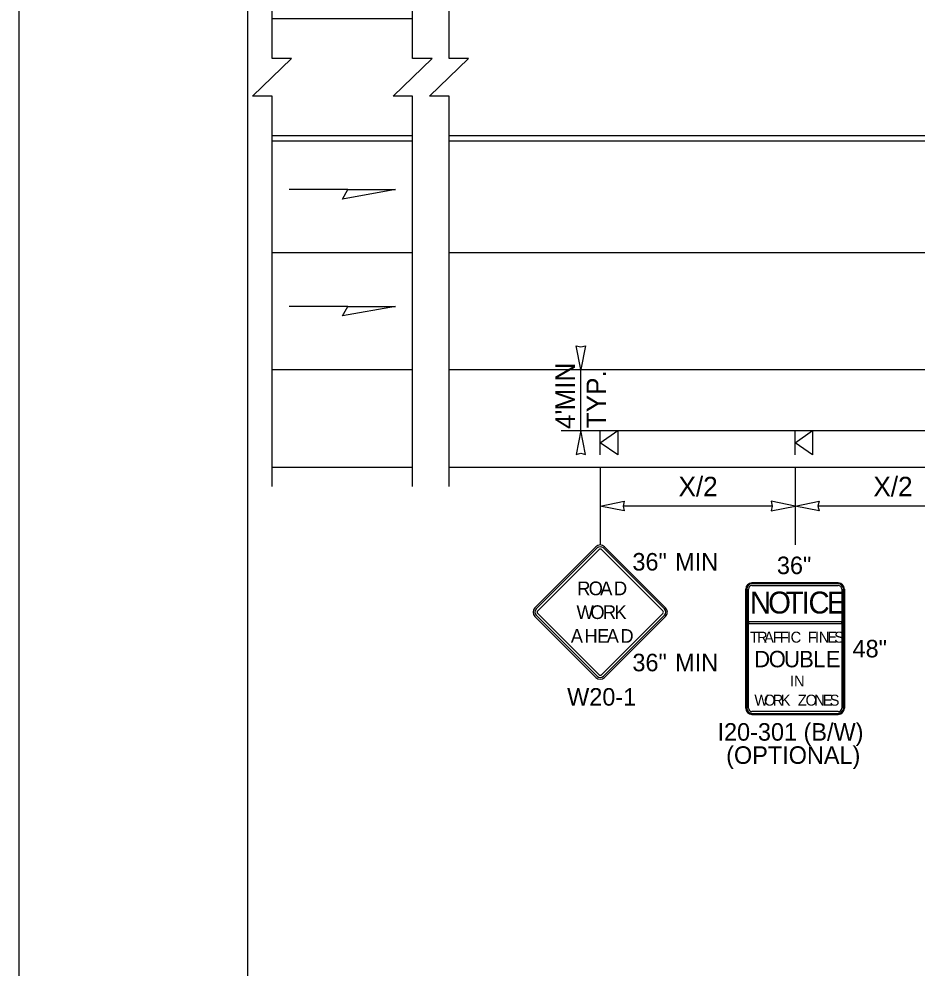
# Model space of a CAD drawing. Extents: x 99999.1 to 100096.1, y 99995 to 100010.7.
# Drawn here: x 100059.062 to 100062.749, y 100002.928 to 100006.826 of the extents above; entities that cross this region are included whole.
import ezdxf

# ---------------------------------------------------------------- set-up
doc = ezdxf.new("R2010")
doc.units = 0
for name, color, linetype in [('RD_ED_ShoulderPavedEdge', 7, 'Continuous'), ('RD_MK_LineEdgeWhite', 7, 'Continuous'), ('RD_MK_LineLane', 7, 'Continuous'), ('RD_MK_LineTwoWayLtTurn', 7, 'Continuous'), ('SH_GI_PlotLimits', 7, 'Continuous'), ('SH_GI_SheetBorder', 7, 'Continuous'), ('TR_SN_ConstructionSigns', 7, 'Continuous'), ('TR_WZ_PortableSignMountBlk-Org', 7, 'Continuous'), ('TR_WZ_PortableSignMountBlk-Wht', 7, 'Continuous'), ('TR_WZ_WorkZoneDetails', 7, 'Continuous'), ('TR_WZ_WorkZoneTextCurrent', 7, 'Continuous')]:
    doc.layers.add(name, color=color, linetype=linetype)

msp = doc.modelspace()

# ---------------------------------------------------------------- linework, layer by layer
at = {"layer": 'RD_ED_ShoulderPavedEdge'}
for p, q in [((100060.1016, 100004.9857), (100060.6783, 100004.9857)), ((100060.8283, 100004.9857), (100074.8933, 100004.9857))]:
    msp.add_line(p, q, dxfattribs=at)
at = {"layer": 'RD_MK_LineEdgeWhite'}
for p, q in [((100060.1016, 100005.3857), (100060.6783, 100005.3857)), ((100060.8283, 100005.3857), (100074.8933, 100005.3857))]:
    msp.add_line(p, q, dxfattribs=at)
at = {"layer": 'RD_MK_LineLane'}
for points in [[(100060.6783, 100005.8657), (100060.1016, 100005.8657)], [(100074.8933, 100005.8657), (100060.8283, 100005.8657)]]:
    msp.add_lwpolyline(points, dxfattribs=at)
at = {"layer": 'RD_MK_LineTwoWayLtTurn'}
for p, q in [((100060.1016, 100006.3257), (100060.6783, 100006.3257)), ((100060.8283, 100006.3257), (100074.8933, 100006.3257))]:
    msp.add_line(p, q, dxfattribs=at)
for points in [[(100060.6783, 100006.8257), (100060.1016, 100006.8257)], [(100060.6783, 100006.3457), (100060.1016, 100006.3457)], [(100074.8933, 100006.3457), (100060.8283, 100006.3457)]]:
    msp.add_lwpolyline(points, dxfattribs=at)
at = {"layer": 'SH_GI_PlotLimits'}
msp.add_lwpolyline([(100059.0625, 99999.6875), (100076.0625, 99999.6875), (100076.0625, 100010.6875), (100059.0625, 100010.6875)], close=True, dxfattribs=at)
at = {"layer": 'SH_GI_SheetBorder'}
msp.add_line((100060, 100010.375), (100060, 100000), dxfattribs=at)
at = {"layer": 'TR_SN_ConstructionSigns'}
for p, q in [((100061.4307, 100004.6583), (100061.1801, 100004.4077)), ((100061.4357, 100004.6533), (100061.1851, 100004.4028)), ((100061.1921, 100004.3958), (100061.4426, 100004.6464)), ((100061.4546, 100004.6464), (100061.7052, 100004.3958)), ((100061.7121, 100004.4028), (100061.4615, 100004.6533)), ((100061.7171, 100004.4077), (100061.4665, 100004.6583)), ((100062.0461, 100003.9953), (100062.0461, 100004.4847)), ((100062.0461, 100004.4847), (100062.0461, 100003.9953)), ((100062.0461, 100004.4847), (100062.0461, 100003.9953)), ((100062.0503, 100004.4847), (100062.0503, 100003.9953)), ((100062.0574, 100004.3504), (100062.0574, 100004.4847)), ((100062.0714, 100004.51), (100062.4258, 100004.51)), ((100062.4258, 100004.51), (100062.0714, 100004.51)), ((100062.4258, 100004.51), (100062.0714, 100004.51)), ((100062.4258, 100004.5058), (100062.0714, 100004.5058)), ((100062.0714, 100004.4988), (100062.4258, 100004.4988)), ((100062.4399, 100004.4847), (100062.4399, 100004.3504)), ((100062.4469, 100003.9953), (100062.4469, 100004.4847)), ((100062.4511, 100004.4847), (100062.4511, 100003.9953)), ((100062.4511, 100003.9953), (100062.4511, 100004.4847)), ((100062.4511, 100003.9953), (100062.4511, 100004.4847)), ((100061.1801, 100004.3719), (100061.4307, 100004.1214)), ((100061.1851, 100004.3769), (100061.4357, 100004.1263)), ((100061.4426, 100004.1333), (100061.1921, 100004.3839)), ((100061.7052, 100004.3839), (100061.4546, 100004.1333)), ((100061.4615, 100004.1263), (100061.7121, 100004.3769)), ((100061.4665, 100004.1214), (100061.7171, 100004.3719)), ((100062.0574, 100004.3504), (100062.0574, 100004.3504)), ((100062.4399, 100004.3504), (100062.0574, 100004.3504)), ((100062.0574, 100004.3504), (100062.0574, 100004.3434)), ((100062.0574, 100004.3434), (100062.0574, 100004.3504)), ((100062.0574, 100004.3434), (100062.4399, 100004.3434)), ((100062.0574, 100003.9953), (100062.0574, 100004.3434)), ((100062.4399, 100004.3434), (100062.4399, 100004.3504)), ((100062.4399, 100004.3504), (100062.4399, 100004.3434)), ((100062.4399, 100004.3434), (100062.4399, 100003.9953)), ((100062.4258, 100003.9813), (100062.0714, 100003.9813)), ((100062.0714, 100003.9742), (100062.4258, 100003.9742)), ((100062.4258, 100003.97), (100062.0714, 100003.97)), ((100062.0714, 100003.97), (100062.4258, 100003.97)), ((100062.0714, 100003.97), (100062.4258, 100003.97))]:
    msp.add_line(p, q, dxfattribs=at)
for centre, radius, start, end in [((100061.4486, 100004.6404), 0.0253, 45, 135), ((100061.4486, 100004.6404), 0.0183, 45, 135), ((100061.4486, 100004.6404), 0.00844, 45, 135), ((100062.0714, 100004.4847), 0.0253, 90, 180), ((100062.0714, 100004.4847), 0.0253, 90, 180), ((100062.0714, 100004.4847), 0.0253, 90, 180), ((100062.0714, 100004.4847), 0.0211, 90, 180), ((100062.0714, 100004.4847), 0.0141, 90, 180), ((100062.4258, 100004.4847), 0.0253, 0, 90), ((100062.4258, 100004.4847), 0.0253, 0, 90), ((100062.4258, 100004.4847), 0.0253, 0, 90), ((100062.4258, 100004.4847), 0.0211, 0, 90), ((100062.4258, 100004.4847), 0.0141, 0, 90), ((100061.198, 100004.3898), 0.0253, 135, 225), ((100061.198, 100004.3898), 0.0183, 135, 225), ((100061.6992, 100004.3898), 0.0183, 315, 45), ((100061.6992, 100004.3898), 0.0253, 315, 45), ((100061.198, 100004.3898), 0.00844, 135, 225), ((100061.6992, 100004.3898), 0.00844, 315, 45), ((100061.4486, 100004.1393), 0.00844, 225, 315), ((100061.4486, 100004.1393), 0.0253, 225, 315), ((100061.4486, 100004.1393), 0.0183, 225, 315), ((100062.0714, 100003.9953), 0.0253, 180, 270), ((100062.0714, 100003.9953), 0.0253, 180, 270), ((100062.0714, 100003.9953), 0.0253, 180, 270), ((100062.0714, 100003.9953), 0.0211, 180, 270), ((100062.0714, 100003.9953), 0.0141, 180, 270), ((100062.4258, 100003.9953), 0.0253, 270, 0), ((100062.4258, 100003.9953), 0.0253, 270, 0), ((100062.4258, 100003.9953), 0.0211, 270, 0), ((100062.4258, 100003.9953), 0.0141, 270, 0), ((100062.4258, 100003.9953), 0.0253, 270, 0)]:
    msp.add_arc(centre, radius, start, end, dxfattribs=at)
at = {"layer": 'TR_WZ_PortableSignMountBlk-Org'}
msp.add_line((100061.4486, 100005.0358), (100061.4486, 100005.1358), dxfattribs=at)
msp.add_lwpolyline([(100061.4486, 100005.0857), (100061.5204, 100005.1358), (100061.5204, 100005.0358)], close=True, dxfattribs=at)
at = {"layer": 'TR_WZ_PortableSignMountBlk-Wht'}
msp.add_line((100062.2486, 100005.0357), (100062.2486, 100005.1357), dxfattribs=at)
msp.add_lwpolyline([(100062.2486, 100005.0856), (100062.3204, 100005.1357), (100062.3204, 100005.0357)], close=True, dxfattribs=at)
at = {"layer": 'TR_WZ_WorkZoneDetails'}
for p, q in [((100060.4123, 100006.125), (100060.1712, 100006.125)), ((100060.4123, 100005.645), (100060.1712, 100005.645)), ((100061.2886, 100005.3857), (100061.4486, 100005.3857)), ((100061.3686, 100005.1358), (100061.3686, 100005.3857)), ((100061.2886, 100005.1358), (100061.4486, 100005.1358)), ((100061.4486, 100005.1358), (100065.9101, 100005.1358)), ((100061.4486, 100004.9857), (100061.4486, 100004.6657)), ((100062.2486, 100004.986), (100062.2486, 100004.6657)), ((100062.1549, 100004.8257), (100061.5423, 100004.8257)), ((100062.9549, 100004.8257), (100062.3423, 100004.8257))]:
    msp.add_line(p, q, dxfattribs=at)
for points in [[(100060.1016, 100004.9057), (100060.1016, 100006.5083), (100060.0216, 100006.5083), (100060.1817, 100006.6632), (100060.1016, 100006.6632), (100060.1016, 100008.2657)], [(100060.6783, 100004.9057), (100060.6783, 100006.5083), (100060.5983, 100006.5083), (100060.7583, 100006.6632), (100060.6783, 100006.6632), (100060.6783, 100008.2657)], [(100060.8283, 100004.9057), (100060.8283, 100006.5083), (100060.7483, 100006.5083), (100060.9083, 100006.6632), (100060.8283, 100006.6632), (100060.8283, 100008.2657)]]:
    msp.add_lwpolyline(points, dxfattribs=at)
for points in [[(100060.6088, 100006.125), (100060.39, 100006.0864), (100060.4123, 100006.125)], [(100060.6088, 100005.645), (100060.39, 100005.6064), (100060.4123, 100005.645)], [(100061.3686, 100005.3857), (100061.3493, 100005.484), (100061.3686, 100005.4795), (100061.3879, 100005.484)], [(100061.3686, 100005.1358), (100061.3493, 100005.0375), (100061.3686, 100005.0421), (100061.3879, 100005.0375)], [(100061.4486, 100004.8257), (100061.5469, 100004.845), (100061.5423, 100004.8257), (100061.5469, 100004.8065)], [(100062.2486, 100004.8257), (100062.1503, 100004.845), (100062.1549, 100004.8257), (100062.1503, 100004.8065)], [(100062.2486, 100004.8257), (100062.3469, 100004.845), (100062.3423, 100004.8257), (100062.3469, 100004.8065)]]:
    msp.add_lwpolyline(points, close=True, dxfattribs=at)

# ---------------------------------------------------------------- texts
at = {"layer": 'TR_SN_ConstructionSigns'}
for s, p in [('36"', (100061.5807, 100004.5607)), ('MIN', (100061.7562, 100004.5607)), ('36"', (100062.1738, 100004.546)), ('48"', (100062.4844, 100004.204)), ('36"', (100061.5807, 100004.147)), ('MIN', (100061.7562, 100004.147)), ('W20-1', (100061.3128, 100004.0059)), ('I20-301 (B/W)', (100061.93, 100003.862)), ('(OPTIONAL)', (100061.9655, 100003.7669))]:
    msp.add_text(s, height=0.072, rotation=360, dxfattribs=at).set_placement(p)
for s, height, p in [('R', 0.0562, (100061.354, 100004.4594)), ('O', 0.0562, (100061.401, 100004.4594)), ('A', 0.0562, (100061.4484, 100004.4594)), ('D', 0.0562, (100061.5049, 100004.4594)), ('N', 0.09, (100062.0629, 100004.3842)), ('O', 0.09, (100062.1379, 100004.3842)), ('T', 0.09, (100062.21, 100004.3842)), ('I', 0.09, (100062.2753, 100004.3842)), ('C', 0.09, (100062.3035, 100004.3842)), ('E', 0.09, (100062.3786, 100004.3842)), ('W', 0.0562, (100061.3511, 100004.3617)), ('O', 0.0562, (100061.408, 100004.3617)), ('R', 0.0562, (100061.4595, 100004.3617)), ('K', 0.0562, (100061.5067, 100004.3617)), ('A', 0.0562, (100061.3277, 100004.264)), ('H', 0.0562, (100061.3839, 100004.264)), ('E', 0.0562, (100061.4357, 100004.264)), ('A', 0.0562, (100061.4751, 100004.264)), ('D', 0.0562, (100061.5313, 100004.264)), ('T', 0.045, (100062.0628, 100004.2646)), ('R', 0.045, (100062.092, 100004.2646)), ('A', 0.045, (100062.1213, 100004.2646)), ('F', 0.045, (100062.1564, 100004.2646)), ('F', 0.045, (100062.1856, 100004.2646)), ('I', 0.045, (100062.2149, 100004.2646)), ('C', 0.045, (100062.2302, 100004.2646)), ('F', 0.045, (100062.3004, 100004.2646)), ('I', 0.045, (100062.3296, 100004.2646)), ('N', 0.045, (100062.3458, 100004.2646)), ('E', 0.045, (100062.3809, 100004.2646)), ('S', 0.045, (100062.4093, 100004.2646)), ('D', 0.0675, (100062.0809, 100004.1634)), ('O', 0.0675, (100062.1403, 100004.1634)), ('U', 0.0675, (100062.2031, 100004.1634)), ('B', 0.0675, (100062.2652, 100004.1634)), ('L', 0.0675, (100062.3225, 100004.1634)), ('E', 0.0675, (100062.3745, 100004.1634)), ('I', 0.045, (100062.2279, 100004.0846)), ('N', 0.045, (100062.2441, 100004.0846)), ('W', 0.045, (100062.0814, 100004.0059)), ('O', 0.045, (100062.121, 100004.0059)), ('R', 0.045, (100062.1566, 100004.0059)), ('K', 0.045, (100062.1894, 100004.0059)), ('Z', 0.045, (100062.2596, 100004.0059)), ('O', 0.045, (100062.2916, 100004.0059)), ('N', 0.045, (100062.3271, 100004.0059)), ('E', 0.045, (100062.3622, 100004.0059)), ('S', 0.045, (100062.3906, 100004.0059))]:
    msp.add_text(s, height=height, dxfattribs=at).set_placement(p)
at = {"layer": 'TR_WZ_WorkZoneTextCurrent'}
for s, rotation, p in [('MIN', 90, (100061.3446, 100005.2182)), ('TYP.', 90, (100061.4726, 100005.1454)), ("4'", 90, (100061.3446, 100005.1417)), ('X/2', 360, (100061.7701, 100004.8657)), ('X/2', 360, (100062.5701, 100004.8657))]:
    msp.add_text(s, height=0.08, rotation=rotation, dxfattribs=at).set_placement(p)

doc.saveas('drawing.dxf')
